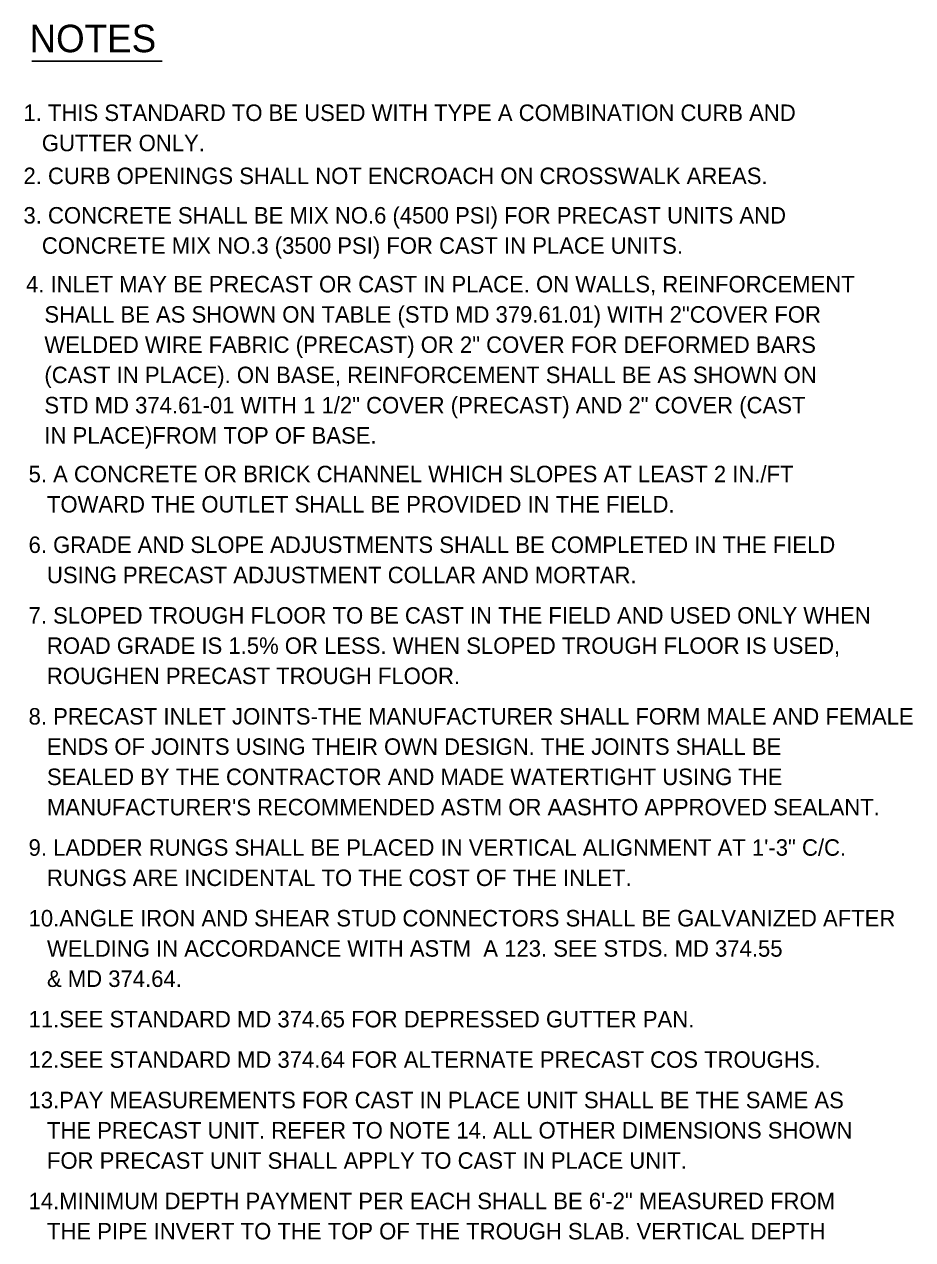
# Model space of a CAD drawing. Extents: x 5.8 to 18, y -5.2 to 5.4.
# Drawn here: x 9.155 to 12.386, y 0.962 to 5.382 of the extents above; entities that cross this region are included whole.
import ezdxf

# ---------------------------------------------------------------- set-up
doc = ezdxf.new("R2010")
doc.units = 0
doc.layers.add('DETL-NOTE', color=7, linetype='Continuous')

msp = doc.modelspace()

# ---------------------------------------------------------------- linework, layer by layer
at = {"layer": 'DETL-NOTE'}
msp.add_line((9.1829, 5.2484), (9.6561, 5.2484), dxfattribs=at)

# ---------------------------------------------------------------- texts
for s, height, p in [('NOTES', 0.1, (9.1742, 5.2805)), ('1. THIS STANDARD TO BE USED WITH TYPE A COMBINATION CURB AND', 0.06, (9.1522, 5.0304)), ('   GUTTER ONLY.', 0.06, (9.1522, 4.9204)), ('2. CURB OPENINGS SHALL NOT ENCROACH ON CROSSWALK AREAS.', 0.06, (9.1522, 4.8009)), ('3. CONCRETE SHALL BE MIX NO.6 (4500 PSI) FOR PRECAST UNITS AND', 0.06, (9.1522, 4.6574)), ('   CONCRETE MIX NO.3 (3500 PSI) FOR CAST IN PLACE UNITS.', 0.06, (9.1522, 4.5474)), ('4. INLET MAY BE PRECAST OR CAST IN PLACE. ON WALLS, REINFORCEMENT ', 0.06, (9.1615, 4.407)), ('   SHALL BE AS SHOWN ON TABLE (STD MD 379.61.01) WITH 2"COVER FOR ', 0.06, (9.1615, 4.297)), ('   WELDED WIRE FABRIC (PRECAST) OR 2" COVER FOR DEFORMED BARS ', 0.06, (9.1615, 4.187)), ('   (CAST IN PLACE). ON BASE, REINFORCEMENT SHALL BE AS SHOWN ON ', 0.06, (9.1615, 4.077)), ('   STD MD 374.61-01 WITH 1 1/2" COVER (PRECAST) AND 2" COVER (CAST ', 0.06, (9.1615, 3.967)), ('   IN PLACE)FROM TOP OF BASE. ', 0.06, (9.1615, 3.857)), ('5. A CONCRETE OR BRICK CHANNEL WHICH SLOPES AT LEAST 2 IN./FT', 0.06, (9.1708, 3.7166)), ('   TOWARD THE OUTLET SHALL BE PROVIDED IN THE FIELD.', 0.06, (9.1708, 3.6066)), ('6. GRADE AND SLOPE ADJUSTMENTS SHALL BE COMPLETED IN THE FIELD', 0.06, (9.1708, 3.4595)), ('   USING PRECAST ADJUSTMENT COLLAR AND MORTAR.', 0.06, (9.1708, 3.3495)), ('7. SLOPED TROUGH FLOOR TO BE CAST IN THE FIELD AND USED ONLY WHEN', 0.06, (9.1708, 3.2025)), ('   ROAD GRADE IS 1.5% OR LESS. WHEN SLOPED TROUGH FLOOR IS USED,', 0.06, (9.1708, 3.0925)), ('   ROUGHEN PRECAST TROUGH FLOOR.', 0.06, (9.1708, 2.9825)), ('8. PRECAST INLET JOINTS-THE MANUFACTURER SHALL FORM MALE AND FEMALE', 0.06, (9.1708, 2.8354)), ('   ENDS OF JOINTS USING THEIR OWN DESIGN. THE JOINTS SHALL BE', 0.06, (9.1708, 2.7254)), ('   SEALED BY THE CONTRACTOR AND MADE WATERTIGHT USING THE', 0.06, (9.1708, 2.6154)), ("   MANUFACTURER'S RECOMMENDED ASTM OR AASHTO APPROVED SEALANT.", 0.06, (9.1708, 2.5054)), ('9. LADDER RUNGS SHALL BE PLACED IN VERTICAL ALIGNMENT AT 1\'-3" C/C.', 0.06, (9.1708, 2.3584)), ('   RUNGS ARE INCIDENTAL TO THE COST OF THE INLET.', 0.06, (9.1708, 2.2484)), ('10.ANGLE IRON AND SHEAR STUD CONNECTORS SHALL BE GALVANIZED AFTER', 0.06, (9.1708, 2.1013)), ('   WELDING IN ACCORDANCE WITH ASTM  A 123. SEE STDS. MD 374.55', 0.06, (9.1708, 1.9913)), ('   & MD 374.64.', 0.06, (9.1708, 1.8813)), ('11.SEE STANDARD MD 374.65 FOR DEPRESSED GUTTER PAN.', 0.06, (9.1708, 1.7342)), ('12.SEE STANDARD MD 374.64 FOR ALTERNATE PRECAST COS TROUGHS.', 0.06, (9.1708, 1.5872)), ('13.PAY MEASUREMENTS FOR CAST IN PLACE UNIT SHALL BE THE SAME AS', 0.06, (9.1708, 1.4401)), ('   THE PRECAST UNIT. REFER TO NOTE 14. ALL OTHER DIMENSIONS SHOWN', 0.06, (9.1708, 1.3301)), ('   FOR PRECAST UNIT SHALL APPLY TO CAST IN PLACE UNIT.', 0.06, (9.1708, 1.2201)), ('14.MINIMUM DEPTH PAYMENT PER EACH SHALL BE 6\'-2" MEASURED FROM', 0.06, (9.1708, 1.0731)), ('   THE PIPE INVERT TO THE TOP OF THE TROUGH SLAB. VERTICAL DEPTH', 0.06, (9.1708, 0.9631))]:
    msp.add_text(s, height=height, dxfattribs=at).set_placement(p)

doc.saveas('drawing.dxf')
